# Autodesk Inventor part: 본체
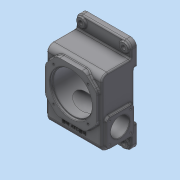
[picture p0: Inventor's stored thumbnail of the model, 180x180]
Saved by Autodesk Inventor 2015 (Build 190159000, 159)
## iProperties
Created: 2026-02
Part Number: 본체
Material: 일반
Document SubType Name: Modeling
Designer: Administrator
Density: 1 g/cm^3
Appearance: 기본값
Author: Administrator
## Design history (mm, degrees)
sketch "스케치1"
  geometry: L1 (59, -72)-(-59, -72); L2 (-59, -72)-(-59, 72); L3 (-59, 72)-(59, 72); L4 (59, 72)-(59, -72); L5 (59, -72)-(-59, 72); L6 (-59, -72)-(59, 72); 1 further point
  constraints: 12 end point, 2 midpoint, 2 parallel, 1 horizontal, 1 perpendicular
  dimensions: "d0" = 118 distance of L2.end L3.end; "d1" = 144 distance of L1.end L2.end
extrude "돌출1" new body sketch "스케치1" distance "d2" = 75; taper "d3" = 0 deg
sketch "스케치2"
  geometry: L1 (55, -42)-(-55, -42); L2 (-55, -42)-(-55, 68); L3 (-55, 68)-(55, 68); L4 (55, 68)-(55, -42); L5 (55, -42)-(-55, 68); L6 (-55, -42)-(55, 68); L7 (59, 72)-(-59, 72) reference; L8 (-59, 72)-(-59, -72) reference; L9 (0, 89)-(0, -89); 7 further points
  constraints: 14 end point, 8 midpoint, 2 parallel, 2 vertical alignment, 1 horizontal, 1 horizontal alignment, 1 perpendicular, 1 vertical
  dimensions: "d4" = 110 distance of L2.end L3.end; "d5" = 110 distance of L1.end L2.end; "d84" = 178 distance of L9.start L9.end; "d86" = 102 distance of L9.end point (0, 13)
extrude "돌출2" join sketch "스케치2" distance "d6" = 7; taper "d7" = 0 deg
chamfer "모따기1" distance "d8" = 25; stored, may be unused: second distance "d9" = 2, angle "d10" = 45 deg
fillet "모깎기1" dims "d11" = 15
fillet "모깎기2" dims "d12" = 13
sketch "스케치3"
  geometry: L1 (-59, -72)-(59, -72) reference; L2 (59, -72)-(59, 72) reference; L3 (59, 72)-(-59, 72) reference; L4 (-59, 72)-(-59, -72) reference; L5 (-59, 102)-(59, 102); L6 (59, 102)-(59, 52); L7 (59, 52)-(-59, 52); L8 (-59, 52)-(-59, 102); L9 (-59, -52)-(59, -52); L10 (59, -52)-(59, -102); L11 (59, -102)-(-59, -102); L12 (-59, -102)-(-59, -52); 1 further point
  constraints: 16 end point, 4 parallel, 3 point on line, 2 horizontal, 2 perpendicular, 1 collinear
  dimensions: "d13" = 118 distance of L5.start L5.end; "d14" = 50 distance of L7.end L5.start; "d15" = 30 distance between parallel lines of L1 L11; "d16" = 30 distance between parallel lines of L3 L5
extrude "돌출3" join sketch "스케치3" distance "d17" = 12; taper "d18" = 0 deg
sketch "스케치4"
  geometry: L1 (75, 161)-(75, -43) reference; L2 (75, 161)-(63, 161) reference; L3 (70, 111)-(75, 111); L4 (75, 111)-(75, 7); L5 (75, 7)-(70, 7); L6 (70, 7)-(70, 111); 3 further points
  constraints: 8 end point, 2 midpoint, 2 parallel, 1 horizontal, 1 horizontal alignment, 1 perpendicular, 1 point on line
  dimensions: "d19" = 5 distance between parallel lines of L1 L6; "d20" = 50 distance between parallel lines of L3 L2
extrude "돌출4" cut sketch "스케치4" stored distance "d21" = 12; taper "d22" = 0 deg
fillet "모깎기3" dims "d23" = 13
fillet "모깎기4" dims "d24" = 3
fillet "모깎기5" dims "d25" = 3
fillet "모깎기6" dims "d26" = 3
sketch "스케치5"
  geometry: L1 (23.787, 68)-(-23.787, 68) reference; L2 (-55, 36.787)-(-55, -10.787) reference; C1 r 45 at (0, 13); 3 further points
  constraints: 2 midpoint, 1 centre point, 1 coincident, 1 horizontal alignment, 1 vertical alignment
  dimensions: "d27" = 90 diameter of C1
extrude "돌출5" cut sketch "스케치5" distance "d28" = 5; taper "d29" = 0 deg
sketch "스케치6"
  geometry: C1 r 45 at (0, 0) reference; C2 r 43 at (0, 0)
  constraints: 1 centre point, 1 coincident
  dimensions: "d30" = 86 diameter of C2
extrude "돌출6" cut sketch "스케치6" distance "d31" = 61; taper "d32" = 0 deg
fillet "모깎기8" dims "d42" = 3
chamfer "모따기2" distance "d43" = 1; stored, may be unused: second distance "d44" = 2, angle "d45" = 45 deg
sketch "스케치9"
  geometry: L1 (37, -24)-(-37, -24); L2 (-37, -24)-(-37, 50); L3 (-37, 50)-(37, 50); L4 (37, 50)-(37, -24); L5 (37, -24)-(-37, 50); L6 (-37, -24)-(37, 50); C1 r 46 at (0, 13) reference; 3 further points
  constraints: 12 end point, 3 coincident, 2 midpoint, 2 parallel, 1 horizontal, 1 perpendicular
  dimensions: "d46" = 74 distance of L2.end L3.end; "d47" = 74 distance of L1.end L2.end
hole "구멍1" sketch "스케치9" at (-37, 50), (37, 50), (37, -24), (-37, -24) diameter "d48" = 4.134; stored, may be unused: countersink angle "d52" = 90 deg, drill point angle "d54" = 118 deg; dims "d49" = 10, "d50" = 4, "d51" = 2, "d53" = 12
sketch "스케치10"
  geometry: L1 (46, -89)-(-46, -89); L2 (-46, -89)-(-46, 89); L3 (-46, 89)-(46, 89); L4 (46, 89)-(46, -89); L5 (46, -89)-(-46, 89); L6 (-46, -89)-(46, 89); C1 r 9 at (-46, 89); C2 r 9 at (46, 89); C3 r 9 at (46, -89); C4 r 9 at (-46, -89); A1 r 10 centre (-46, 89) between (-46, 99) and (-56, 89) reference; 1 further point
  constraints: 12 end point, 4 centre point, 4 coincident, 2 midpoint, 2 parallel, 1 horizontal, 1 perpendicular
  dimensions: "d55" = 92 distance of L2.end L3.end (derived); "d56" = 178 distance of L1.end L2.end (derived); "d57" = 18 diameter of C1; "d58" = 18 diameter of C2; "d59" = 18 diameter of C3; "d60" = 18 diameter of C4
extrude "돌출8" join sketch "스케치10" distance "d61" = 3; taper "d62" = 0 deg
fillet "모깎기9" dims "d63" = 3
sketch "스케치11"
  geometry: L1 (46, -89)-(-46, -89); L2 (-46, -89)-(-46, 89); L3 (-46, 89)-(46, 89); L4 (46, 89)-(46, -89); L5 (46, -89)-(-46, 89); L6 (-46, -89)-(46, 89); A1 r 9 centre (-46, 89) between (-41.025, 96.5) and (-53.5, 84.025) reference; 5 further points
  constraints: 12 end point, 4 coincident, 2 midpoint, 2 parallel, 1 horizontal, 1 perpendicular
hole "구멍3" sketch "스케치11" at (-46, 89), (46, 89), (46, -89), (-46, -89) diameter "d73" = 9; stored, may be unused: countersink angle "d77" = 90 deg, drill point angle "d79" = 118 deg; dims "d74" = 10, "d75" = 4, "d76" = 2, "d78" = 12
node "작업 평면1"
sketch "스케치13"
  geometry: L1 (82.787, 74)-(82.787, 10) reference; L2 (78.787, 4.343)-(78.787, 0) reference; L3 (78.787, 0)-(69.787, 0) reference; L4 (69.787, 0)-(68.787, 1) reference; L5 (68.787, 1)-(68.787, 5) reference; L6 (68.787, 5)-(66.787, 5) reference; L7 (66.787, 5)-(66.787, 63) reference; L8 (63.787, 66)-(-16.213, 66) reference; L9 (-19.213, 63)-(-19.213, 5) reference; L10 (-19.213, 5)-(-21.213, 5) reference; L11 (-21.213, 5)-(-21.213, 1) reference; L12 (-21.213, 1)-(-22.213, 0) reference; L13 (-22.213, 0)-(-31.213, 0) reference; L14 (-31.213, 0)-(-31.213, 4.343) reference; L15 (-35.213, 10)-(-35.213, 74) reference; L16 (-32.213, 77)-(79.787, 77) reference; L17 (-7.213, 66)-(-1.213, 60); L18 (-1.213, 60)-(23.787, 60); L19 (23.787, 60)-(23.787, 66); A1 r 3 centre (79.787, 74) between (82.787, 74) and (79.787, 77) reference; A2 r 3 centre (79.787, 10) between (80.787, 7.172) and (82.787, 10) reference; A3 r 3 centre (81.787, 4.343) between (80.787, 7.172) and (78.787, 4.343) reference; A4 r 3 centre (63.787, 63) between (66.787, 63) and (63.787, 66) reference; A5 r 3 centre (-16.213, 63) between (-16.213, 66) and (-19.213, 63) reference; A6 r 3 centre (-34.213, 4.343) between (-31.213, 4.343) and (-33.213, 7.172) reference; A7 r 3 centre (-32.213, 10) between (-35.213, 10) and (-33.213, 7.172) reference; A8 r 3 centre (-32.213, 74) between (-32.213, 77) and (-35.213, 74) reference; 1 further point
  constraints: 6 end point, 1 horizontal, 1 midpoint, 1 point on line, 1 vertical alignment
  dimensions: "d87" = 45 deg angle of L19 L17; "d88" = 50 diameter of L17.end L19; "d89" = 6 distance between parallel lines of L18 L8
revolve "회전2" sketch "스케치13" stored, may be unused: angle "d90" = 90 deg
sketch "스케치14"
  geometry: C1 r 25 at (0, 0) reference; C2 r 20 at (0, 0); 1 further point
  constraints: 1 centre point, 1 coincident
  dimensions: "d91" = 40 diameter of C2
extrude "돌출9" cut sketch "스케치14" distance "d92" = 11; taper "d93" = 0 deg
fillet "모깎기10" dims "d94" = 1.5
chamfer "모따기3" distance "d95" = 1; stored, may be unused: second distance "d96" = 2, angle "d97" = 45 deg
sketch "스케치12"
  geometry: L1 (0, 0)-(0, 118) reference; L2 (72, 4)-(72, -30) reference; L3 (3, 51)-(61, 51); L4 (61, 51)-(61, -7); L5 (61, -7)-(3, -7); L6 (3, -7)-(3, 51); L7 (32, 51)-(32, -7); L8 (61, 22)-(3, 22); L9 (63, -30)-(63, -16) reference; L10 (57, -10)-(10, -10) reference; L11 (0, 0)-(0, 118) reference; L12 (57, 128)-(10, 128) reference; L13 (63, 134)-(63, 148) reference; L14 (72, 148)-(63, 148) reference; L15 (72, 148)-(72, 114) reference; L16 (70, 114)-(72, 114) reference; L17 (64, 10)-(64, 108) reference; L18 (72, 4)-(70, 4) reference; L19 (72, 4)-(72, -30) reference; L20 (72, -30)-(63, -30) reference; L21 (63, -30)-(63, -16) reference; L22 (57, -10)-(10, -10) reference; L23 (0, 0)-(0, 118) reference; L24 (57, 128)-(10, 128) reference; L25 (63, 134)-(63, 148) reference; L26 (72, 148)-(63, 148) reference; L27 (72, 148)-(72, 114) reference; L28 (70, 114)-(72, 114) reference; L29 (64, 10)-(64, 108) reference; L30 (72, 4)-(70, 4) reference; L31 (72, 4)-(72, -30) reference; L32 (72, -30)-(63, -30) reference; L33 (-10, 48.213)-(-10, 95.787) reference; L34 (-10, 72)-(0, 72); A1 r 6 centre (57, -16) between (63, -16) and (57, -10) reference; A2 r 10 centre (10, 0) between (0, 0) and (10, -10) reference; A3 r 10 centre (10, 118) between (10, 128) and (0, 118) reference; A4 r 6 centre (57, 134) between (57, 128) and (63, 134) reference; A5 r 6 centre (70, 108) between (70, 114) and (64, 108) reference; A6 r 6 centre (70, 10) between (64, 10) and (70, 4) reference; A7 r 6 centre (57, -16) between (63, -16) and (57, -10) reference; A8 r 10 centre (10, 0) between (0, 0) and (10, -10) reference; A9 r 10 centre (10, 118) between (10, 128) and (0, 118) reference; A10 r 6 centre (57, 134) between (57, 128) and (63, 134) reference; A11 r 6 centre (70, 108) between (70, 114) and (64, 108) reference; A12 r 6 centre (70, 10) between (64, 10) and (70, 4) reference; 1 further point
  constraints: 14 end point, 5 midpoint, 2 parallel, 2 perpendicular, 1 horizontal, 1 point on line
  dimensions: "d80" = 58 distance of L4.end L5.end; "d81" = 58 distance of L3.end L4.end; "d82" = 40 distance between parallel lines of L2 L7; "d98" = 50 distance between parallel lines of L8 L34
extrude "돌출10" join sketch "스케치12" distance "d99" = 5; taper "d100" = 0 deg
fillet "모깎기11" dims "d101" = 7
fillet "모깎기12" dims "d102" = 3
sketch "스케치15"
  geometry: L1 (61, 0)-(61, 44) reference; L2 (54, 51)-(10, 51) reference; C1 r 20 at (32, 22); 3 further points
  constraints: 2 midpoint, 1 centre point, 1 horizontal alignment, 1 vertical alignment
  dimensions: "d103" = 40 diameter of C1
extrude "돌출11" cut sketch "스케치15" stored distance "d104" = 5; taper "d105" = 0 deg
sketch "스케치16"
  geometry: L1 (54, 0)-(10, 0); L2 (10, 0)-(10, 44); L3 (10, 44)-(54, 44); L4 (54, 44)-(54, 0); L5 (54, 0)-(10, 44); L6 (10, 0)-(54, 44); C1 r 20 at (32, 22) reference; A1 r 7 centre (10, 44) between (10, 51) and (3, 44) reference; 5 further points
  constraints: 12 end point, 4 coincident, 2 midpoint, 2 parallel, 1 horizontal, 1 perpendicular
  dimensions: "d106" = 44 distance of L2.end L3.end (derived); "d107" = 44 distance of L1.end L2.end (derived)
hole "구멍4" sketch "스케치16" at (10, 44), (54, 44), (54, 0), (10, 0) diameter "d108" = 3.242; stored, may be unused: countersink angle "d112" = 90 deg, drill point angle "d114" = 118 deg; dims "d109" = 8, "d110" = 4, "d111" = 2, "d113" = 10
node "작업 평면2"
fillet "모깎기13" dims "d115" = 7
fillet "모깎기14" dims "d116" = 3
chamfer "모따기4" distance "d117" = 1; stored, may be unused: second distance "d118" = 2, angle "d119" = 45 deg
node "작업 평면3"
sketch "스케치17"
  geometry: L1 (-46, 13)-(0, 13); 2 further points
  constraints: 2 end point, 1 horizontal, 1 horizontal alignment, 1 vertical alignment, 2 other
  dimensions: "d121" = 65 distance of point (0, -52) L1.end
feature "엠보싱1" sketch "스케치17" dims "d122" = 0.5, "d123" = 0
fillet "모깎기15" dims "d124" = 3
node "솔리드1"
mirror "대칭1"
node "절단 모서리 투영2"
node "절단 모서리 투영3"
node "절단 모서리 투영4"
